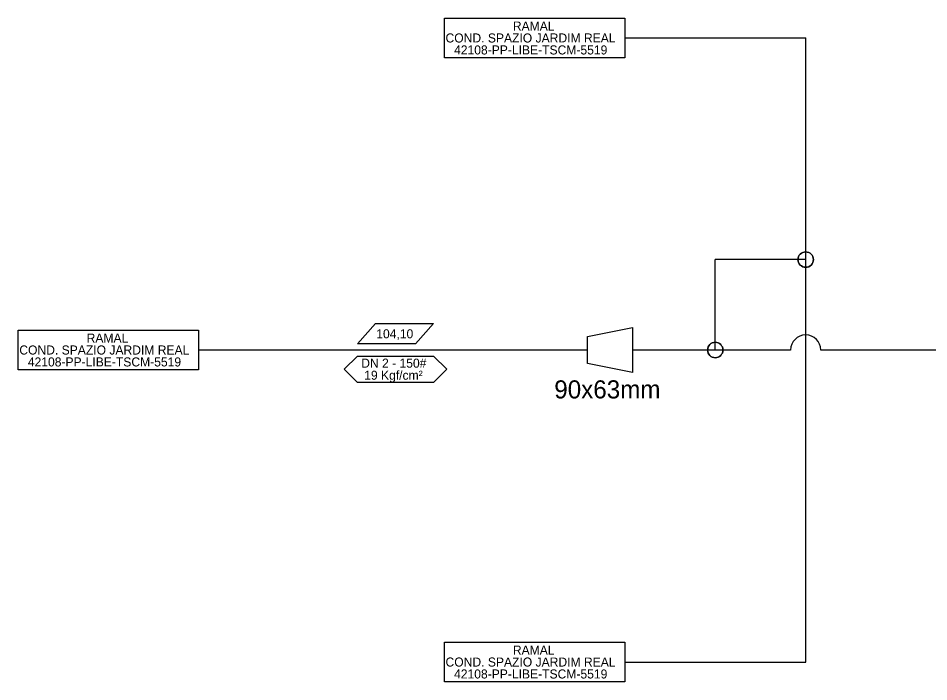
# Model space of a CAD drawing. Extents: x 656692 to 673945, y 7585994 to 7599066.
# Drawn here: x 671225.8 to 671527.8, y 7594446.4 to 7594666.6 of the extents above; entities that cross this region are included whole.
import ezdxf

# ---------------------------------------------------------------- set-up
doc = ezdxf.new("R2010")
doc.units = 0
for name, color, linetype in [('SIMBOLO', 7, 'Continuous'), ('TEXTO', 7, 'Continuous'), ('TUBO_PEAD_GN_63', 7, 'Continuous'), ('TUBO_PEAD_GN_90', 7, 'Continuous')]:
    doc.layers.add(name, color=color, linetype=linetype)

# ---------------------------------------------------------------- blocks, each defined once
blk = doc.blocks.new('INTERLIGACAO_5')
at = {"layer": 'SIMBOLO'}
blk.add_circle((0, 0), 1.28, dxfattribs=at)
for start, end in [(0, 180), (180, 0)]:
    blk.add_arc((0, 0), 1.28, start, end, dxfattribs=at)

msp = doc.modelspace()

# ---------------------------------------------------------------- linework, layer by layer
at = {"layer": 'SIMBOLO'}
for points in [[(671367.14, 7594666.57), (671426.97, 7594666.57), (671426.97, 7594653.44), (671367.14, 7594653.44)], [(671357.55, 7594558.48), (671338.33, 7594558.48), (671344.33, 7594565.23), (671363.55, 7594565.23)], [(671225.78, 7594563.04), (671285.61, 7594563.04), (671285.61, 7594549.92), (671225.78, 7594549.92)], [(671429.56, 7594548.98), (671414.56, 7594551.98), (671414.56, 7594560.98), (671429.56, 7594563.98)], [(671367.14, 7594459.52), (671426.97, 7594459.52), (671426.97, 7594446.39), (671367.14, 7594446.39)]]:
    msp.add_lwpolyline(points, close=True, dxfattribs=at)
msp.add_lwpolyline([(671367.94, 7594550.11), (671363.57, 7594545.73), (671338.32, 7594545.73), (671333.94, 7594550.11), (671338.32, 7594554.48), (671363.57, 7594554.48), (671367.94, 7594550.11)], dxfattribs=at)
at = {"layer": 'TUBO_PEAD_GN_63'}
msp.add_line((671414.56, 7594556.48), (671285.61, 7594556.48), dxfattribs=at)
at = {"layer": 'TUBO_PEAD_GN_90'}
for p, q in [((671426.97, 7594660.01), (671486.97, 7594660.01)), ((671486.97, 7594452.95), (671486.97, 7594660.01)), ((671456.97, 7594556.48), (671456.97, 7594586.48)), ((671486.97, 7594586.48), (671456.97, 7594586.48)), ((671481.97, 7594556.48), (671429.56, 7594556.48)), ((671621.76, 7594556.48), (671491.97, 7594556.48)), ((671426.97, 7594452.95), (671486.97, 7594452.95))]:
    msp.add_line(p, q, dxfattribs=at)
msp.add_arc((671486.97, 7594556.48), 5, 0, 180, dxfattribs=at)

# ---------------------------------------------------------------- block references
at = {"layer": 'SIMBOLO', "xscale": 2, "yscale": 2}
for p in [(671486.97, 7594586.48), (671456.97, 7594556.48)]:
    msp.add_blockref('INTERLIGACAO_5', p, dxfattribs=at)

# ---------------------------------------------------------------- texts
at = {"layer": 'TEXTO'}
for s, height, p in [('RAMAL', 3, (671389.84, 7594662.47)), ('COND. SPAZIO JARDIM REAL', 3, (671367.51, 7594658.51)), ('42108-PP-LIBE-TSCM-5519', 3, (671370.34, 7594654.54)), ('RAMAL', 3, (671248.47, 7594558.94)), ('104,10', 3, (671344.54, 7594560.36)), ('COND. SPAZIO JARDIM REAL', 3, (671226.15, 7594554.98)), ('42108-PP-LIBE-TSCM-5519', 3, (671228.97, 7594551.02)), ('DN 2 - 150#', 3, (671339.54, 7594550.62)), ('19 Kgf/cm²', 3, (671340.54, 7594546.61)), ('90x63mm', 6, (671403.58, 7594540.41)), ('RAMAL', 3, (671389.84, 7594455.42)), ('COND. SPAZIO JARDIM REAL', 3, (671367.51, 7594451.45)), ('42108-PP-LIBE-TSCM-5519', 3, (671370.34, 7594447.49))]:
    msp.add_text(s, height=height, dxfattribs=at).set_placement(p)

doc.saveas('drawing.dxf')
